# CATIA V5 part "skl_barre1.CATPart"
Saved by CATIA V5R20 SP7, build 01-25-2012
Part number: skl_barre1
Publications: "axe_pivot_1_2", "axe_pivot_1_0", "PlanRef", "PointA", "PointB"
Bounding box of the stored display mesh (mm): x 0 to 20, y 0 to 95.011, z -31.191 to 0
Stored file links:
  U:\Projet IAO\omeyer\Catia\skl_barre1.CATPart
  U:\Projet IAO\omeyer\Catia\skl_748.CATProduct
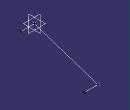
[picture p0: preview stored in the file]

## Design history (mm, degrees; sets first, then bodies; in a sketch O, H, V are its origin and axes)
Set1
  Point1 "PointA": linked copy from another document
  Point2 "PointB": linked copy from another document
  Plane1 "PlanRef": linked copy from another document
Set2
  Line1: type PtPt, FirstPoint Point1, SecondPoint Point2
  Line2 "axe_pivot_1_2": type Normal, RefPoint Point2, RefSkin Plane1, Start 0, End 20
  Line3 "axe_pivot_1_0": type Normal, RefPoint Point1, RefSkin Plane1, Start 0, End 20
Body1 (main body)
